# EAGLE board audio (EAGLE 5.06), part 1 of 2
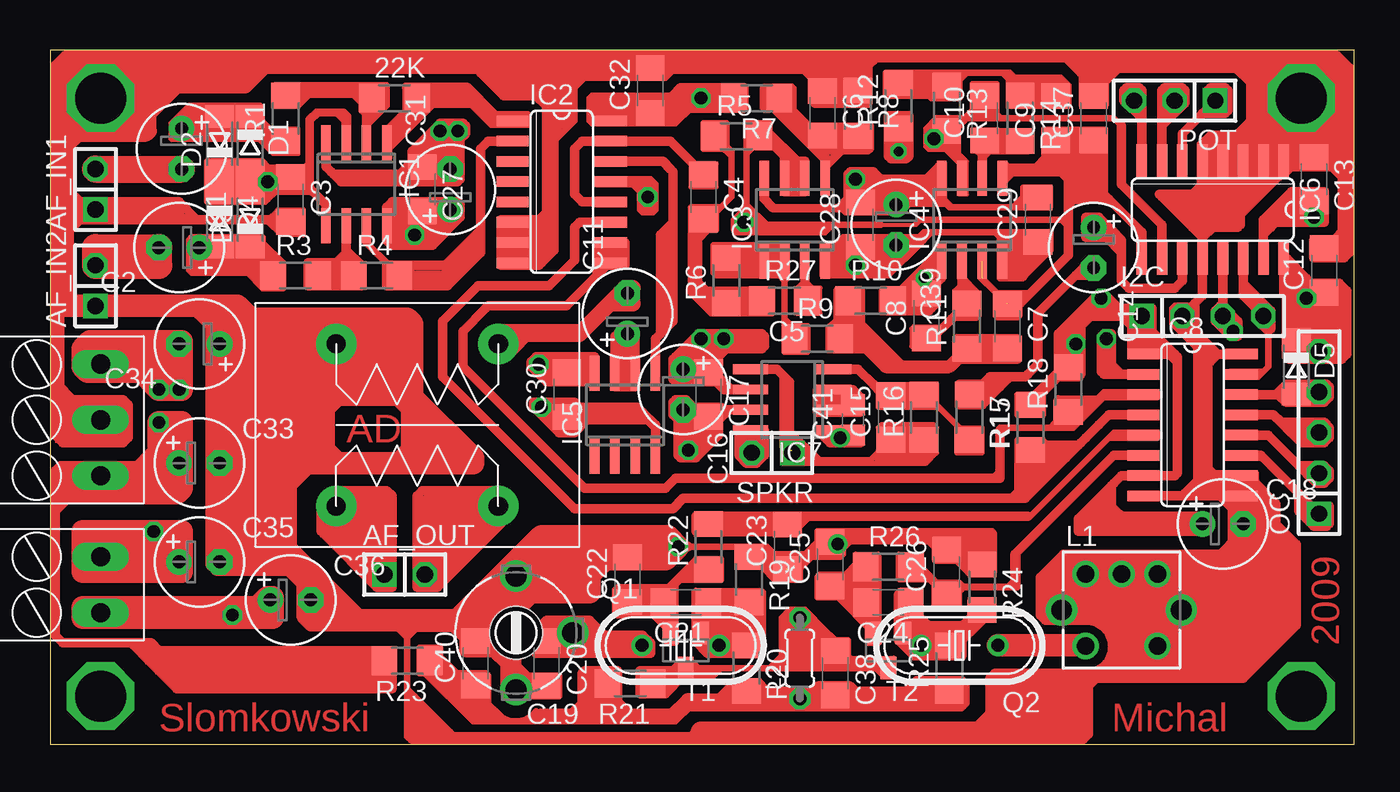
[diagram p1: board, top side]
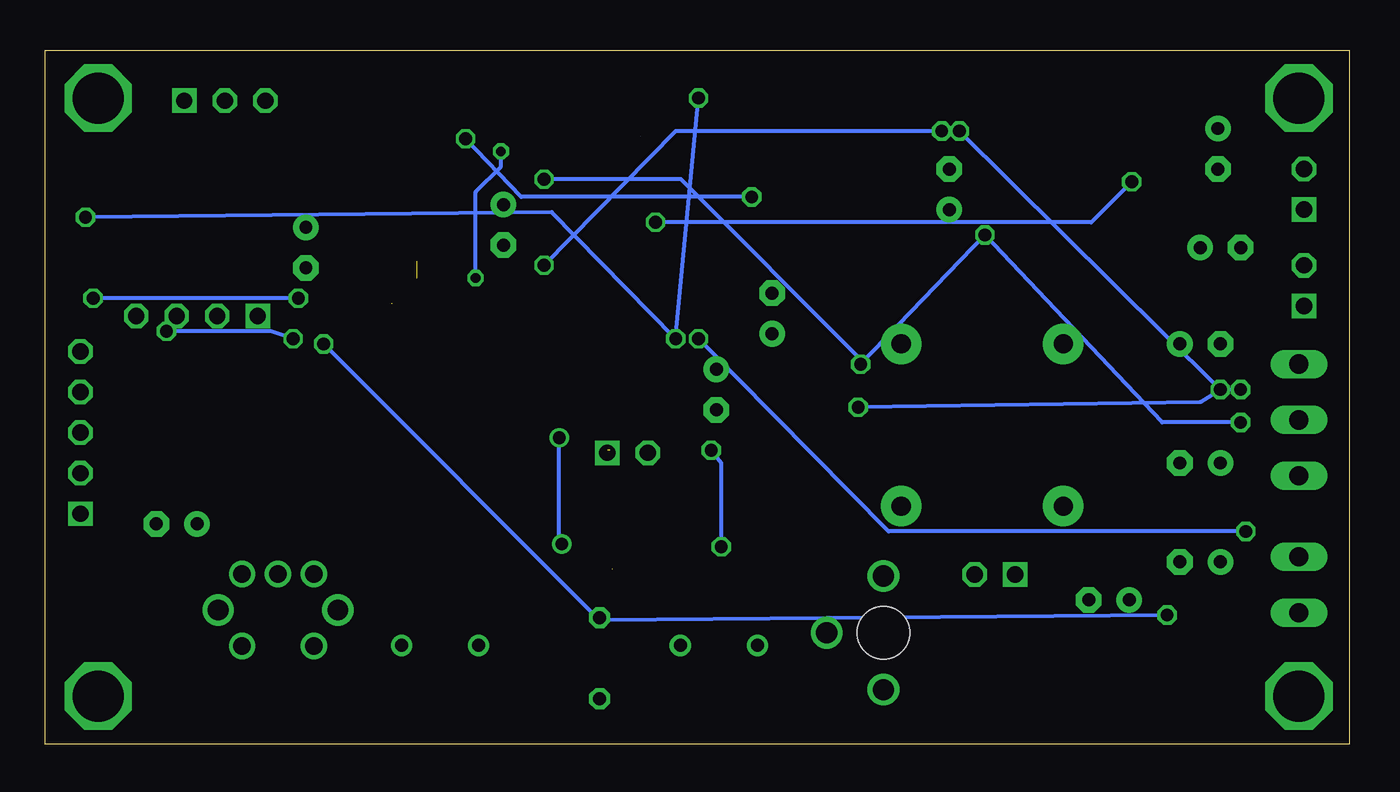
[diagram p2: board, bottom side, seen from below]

Size 81.74 x 43.48 mm. Coordinates in mm from the lower left corner, seen from the top.
Outline: 0,0 81.74,0 81.74,43.48 0,43.48 0,0
Copper layers (1*16): Top 0.035mm / dielectric 1.5mm / Bottom 0.035mm
Design rules "default": minimum track width 10mil, minimum drill 24mil, track to track 8mil, track to pad 8mil, pad to pad 8mil, via to via 8mil, smd to smd 8mil, copper to edge 40mil, drill to drill 8mil, minimum pad ring 10mil, minimum via ring 8mil, stop-mask expansion 4mil, vias tented up to drill 0mil, thermal gap 10mil

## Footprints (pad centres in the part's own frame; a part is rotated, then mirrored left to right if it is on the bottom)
R1206 = smd 1.6 x 1.803: 1 -1.422,0; 2 1.422,0
1X02 = drill 1.016 square: 1 -1.27,0 | drill 1.016 octagon: 2 1.27,0
E2,5-6 = drill 0.813 pad 1.6 round: + -1.27,0 | drill 0.813 pad 1.6 octagon: - 1.27,0
C1206 = smd 1.6 x 1.8: 1 -1.4,0; 2 1.4,0
CTRIM808-1 = drill 1.321 round: 1 -3.556,0; 2 0,-3.556; 3 3.556,0 | hole 3.302: 0,0
C0805 = smd 1.3 x 1.5: 1 -0.95,0; 2 0.95,0
SOD80C = smd 1.4 x 1.8: A 1.7,0; C -1.7,0
1X04 = drill 1.016 square: 1 -3.81,0 | drill 1.016 octagon: 2 -1.27,0; 3 1.27,0; 4 3.81,0
SO08 = smd 0.6 x 2.2: 1 -1.905,-2.6; 2 -0.635,-2.6; 3 0.635,-2.6; 4 1.905,-2.6; 5 1.905,2.6; 6 0.635,2.6; 7 -0.635,2.6; 8 -1.905,2.6
SO16 = smd 0.66 x 2.032: 1 -4.445,-3.073; 2 -3.175,-3.073; 3 -1.905,-3.073; 4 -0.635,-3.073; 5 0.635,-3.073; 6 1.905,-3.073; 7 3.175,-3.073; 8 4.445,-3.073; 9 4.445,3.073; 10 3.175,3.073; 11 1.905,3.073; 12 0.635,3.073; 13 -0.635,3.073; 14 -1.905,3.073; 15 -3.175,3.073; 16 -4.445,3.073
71K = drill 1.1 round: 1 -2.25,-2.25; 2 -2.25,2.25; 3 0,2.25; 4 2.25,2.25; 5 2.25,-2.25 | drill 1.3 round: S1 -3.75,0; S2 3.75,0
0204/5 = drill 0.813 octagon: 1 -2.54,0; 2 2.54,0
1X05 = drill 1.016 square: 1 -5.08,0 | drill 1.016 octagon: 2 -2.54,0; 3 0,0; 4 2.54,0; 5 5.08,0
1X03 = drill 1.016 square: 1 -2.54,0 | drill 1.016 octagon: 2 0,0; 3 2.54,0
HC49U-V = drill 0.813 round: 1 -2.413,0; 2 2.413,0
SOT23 = smd 1 x 1.4: 1 -0.95,-1.1; 2 0.95,-1.1; 3 0,1.1
TRANSFORMER = drill 1.2 pad 2.54 round: 1 -5.08,-5.08; 2 5.08,-5.08; 3 5.08,5.08; 4 -5.08,5.08
RIACON-3 = drill 1.2 long: P$1 0,-3.5; P$2 0,0; P$3 0,3.5
RIACON-2 = drill 1.2 long: P$1 0,1.75; P$2 0,-1.75

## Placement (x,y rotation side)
22K  [R1206]  21.58,40.47 0 top
AF_IN1  [1X02]  2.85,34.76 90 top
AF_IN2  [1X02]  2.85,28.73 90 top
AF_OUT  [1X02]  22.22,10.63 0 top
C1  47u  [E2,5-6]  8.25,37.3 270 top
C2  47u  [E2,5-6]  8.09,31.11 180 top
C3  100n  [C1206]  15.08,34.12 270 top
C4  100n  [C1206]  40.95,34.28 270 top
C5  100n  [C1206]  46.03,27.77 180 top
C6  100n  [C1206]  48.41,39.52 270 top
C7  10n  [C1206]  60,26.19 270 top
C8  10n  [C1206]  54.92,26.82 90 top
C9  10n  [C1206]  63.02,39.2 90 top
C10  10n  [C1206]  58.57,39.2 90 top
C11  47u  [E2,5-6]  36.19,26.98 90 top
C12  100n  [C1206]  79.85,29.68 90 top
C13  100n  [C1206]  79.21,35.39 270 top
C14  47u  [E2,5-6]  65.4,31.11 270 top
C15  100p  [C1206]  52.7,20.47 90 top
C16  47u  [E2,5-6]  39.68,22.22 270 top
C17  100n  [C1206]  41.27,21.9 270 top
C18  47u  [E2,5-6]  73.5,13.81 0 top
C19  30p  [CTRIM808-1]  29.21,6.98 90 top
C20  10p  [C1206]  31.11,5.07 270 top
C21  100p  [C1206]  39.84,8.88 180 top
C22  100p  [C1206]  36.19,10.31 90 top
C23  10n  [C1206]  46.19,12.38 90 top
C24  100p  [C1206]  52.54,8.88 180 top
C25  100p  [C1206]  48.89,11.26 90 top
C26  10n  [C1206]  56.19,10.79 90 top
C27  100n  [C1206]  23.33,34.76 270 top
C28  100n  [C1206]  50.8,32.54 90 top
C29  100n  [C1206]  61.91,32.85 90 top
C30  100n  [C1206]  32.38,21.9 90 top
C31  47u  [E2,5-6]  25.08,34.76 90 top
C32  100n  [C1206]  37.62,40.95 90 top
C33  47u  [E2,5-6]  9.36,17.61 0 top
C34  47u  [E2,5-6]  9.36,25.08 180 top
C35  47u  [E2,5-6]  9.36,11.42 0 top
C36  47u  [E2,5-6]  15.08,9.04 0 top
C37  100n  [C1206]  65.4,39.2 90 top
C38  115p  [C1206]  49.21,4.44 270 top
C39  47u  [E2,5-6]  53.02,32.54 270 top
C40  100n  [C1206]  26.67,5.07 90 top
C41  10n  [C0805]  50.32,20.31 90 top
D1  [SOD80C]  12.54,37.62 270 top
D2  [SOD80C]  10.63,37.62 90 top
D3  [SOD80C]  12.54,32.85 90 top
D4  [SOD80C]  10.63,32.85 270 top
D5  [SOD80C]  78.1,23.65 270 top
I2C  [1X04]  72.23,26.82 0 top
IC1  NE5532D  [SO08]  19.2,35.08 180 top
IC2  4053D  [SO16]  32.06,34.6 270 top
IC3  TL072D  [SO08]  46.67,32.85 0 top
IC4  TL072D  [SO08]  57.78,32.85 0 top
IC5  TL072D  [SO08]  36.03,20.63 0 top
IC6  DS1881  [SO16]  72.86,33.49 180 top
IC7  MAX4364  [SO08]  46.51,21.58 90 top
IC8  TPIC2810  [SO16]  71.59,20 270 top
L1  [71K]  67.15,8.41 0 top
L2  2.7u  [0204/5]  46.99,5.39 90 top
OC  [1X05]  79.53,19.52 90 top
POT  [1X03]  70.48,40.32 180 top
Q1  [HC49U-V]  39.52,6.18 0 top
Q2  [HC49U-V]  56.99,6.18 180 top
R1  10k  [R1206]  14.76,39.2 90 top
R3  10k  [R1206]  15.39,29.36 0 top
R4  [R1206]  20.47,29.36 0 top
R5  10k  [R1206]  43.02,38.09 0 top
R6  10k  [R1206]  42.38,29.04 90 top
R7  10k  [R1206]  44.29,40.48 180 top
R8  10k  [R1206]  50.64,39.52 270 top
R9  4k7  [R1206]  48.1,25.39 0 top
R10  4k7  [R1206]  51.43,27.77 0 top
R11  1k5  [R1206]  57.46,26.19 90 top
R12  4k7  [R1206]  53.18,40 90 top
R13  4k7  [R1206]  56.19,39.84 270 top
R14  1k5  [R1206]  60.8,39.2 270 top
R15  22k  [R1206]  57.62,20.47 270 top
R16  47k  [R1206]  54.76,20.47 90 top
R17  10k  [R1206]  61.43,19.84 90 top
R18  10k  [R1206]  63.81,22.22 90 top
R19  47k  [R1206]  43.81,10.31 270 top
R20  100k  [R1206]  43.65,4.76 270 top
R21  2k2  [R1206]  36.35,3.8 180 top
R22  1k  [R1206]  41.27,12.38 90 top
R23  100  [R1206]  22.38,5.23 180 top
R24  47k  [R1206]  58.41,9.84 270 top
R25  100k  [R1206]  56.35,4.76 90 top
R26  1k  [R1206]  52.54,11.11 0 top
R27  1M  [R1206]  46.03,27.77 0 top
SPKR  [1X02]  45.24,18.25 180 top
T1  BC847  [SOT23]  39.84,5.87 180 top
T2  BC847  [SOT23]  52.54,5.87 180 top
TR1  [TRANSFORMER]  23.01,20 180 top
U$1  RIACON-3  [RIACON-3]  3.17,20.31 0 top
U$2  RIACON-2  [RIACON-2]  3.17,9.99 0 top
